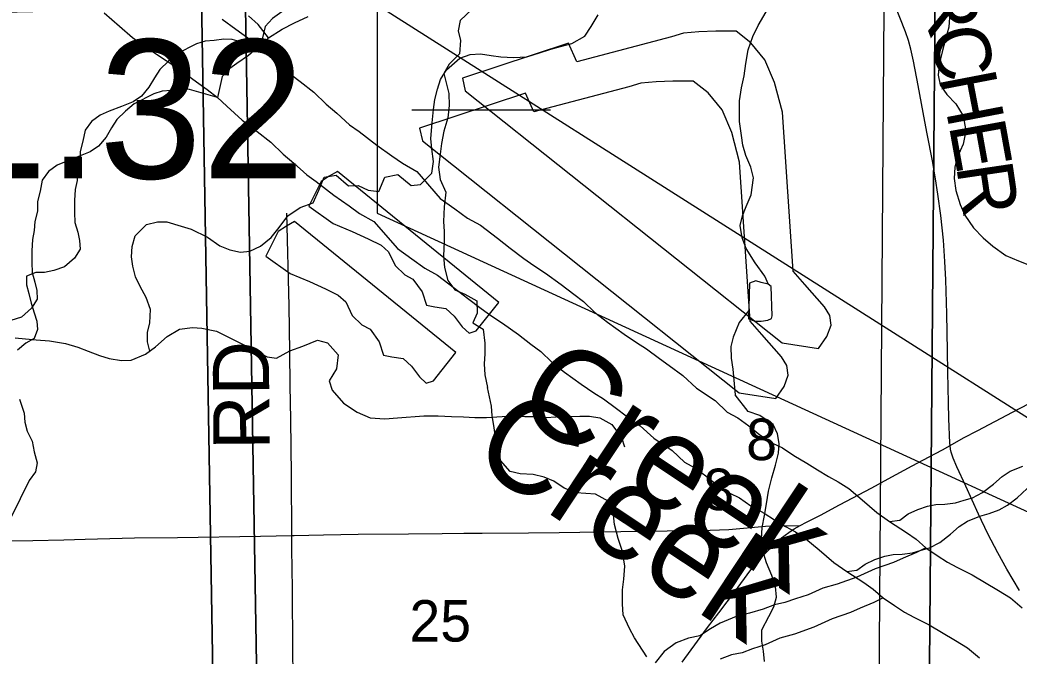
# Model space of a CAD drawing. Extents: x -21.1 to 50.3, y -4.9 to 22.1.
# Drawn here: x 3.578 to 4.587, y 17.259 to 17.902 of the extents above; entities that cross this region are included whole.
import ezdxf

# ---------------------------------------------------------------- set-up
doc = ezdxf.new("R2010")
doc.units = 0
for name, color, linetype in [('GM_X_County_Road', 7, 'Continuous'), ('GM_X_County_Road_Text', 7, 'Continuous'), ('GM_X_Major_River', 7, 'Continuous'), ('GM_X_Major_River_Text', 7, 'Continuous'), ('GM_X_Minor_Lake', 7, 'Continuous'), ('GM_X_Minor_River', 7, 'Continuous'), ('GM_X_Section', 7, 'Continuous'), ('GM_X_Section_Text', 7, 'Continuous'), ('GM_X_Township_Road', 7, 'Continuous'), ('GM_X_Township_Road_Text', 7, 'Continuous'), ('SH_Data', 7, 'Continuous')]:
    doc.layers.add(name, color=color, linetype=linetype)

msp = doc.modelspace()

# ---------------------------------------------------------------- linework, layer by layer
at = {"layer": 'GM_X_County_Road'}
for points in [[(3.853, 17.3809), (3.8526, 17.4422), (3.8524, 17.4702), (3.8521, 17.4981), (3.8515, 17.5323), (3.851, 17.5664), (3.8503, 17.613), (3.848, 17.7066)], [(3.8616, 16.8749), (3.8613, 16.8772), (3.8595, 16.8957), (3.8585, 16.9112), (3.8578, 16.9391), (3.8577, 16.9546), (3.8575, 16.9794), (3.8568, 17.026), (3.8566, 17.0509), (3.8566, 17.0695), (3.8562, 17.1068), (3.856, 17.1316), (3.8555, 17.1627), (3.8551, 17.1875), (3.8548, 17.2154), (3.8541, 17.2651), (3.8536, 17.3273), (3.8531, 17.3677), (3.853, 17.3809)]]:
    msp.add_lwpolyline(points, dxfattribs=at)
at = {"layer": 'GM_X_Major_River'}
for points in [[(3.6634, 17.9087), (3.6791, 17.8952), (3.692, 17.8839), (3.7054, 17.8745), (3.7165, 17.867), (3.726, 17.8606), (3.7394, 17.852), (3.7531, 17.8419), (3.7676, 17.8314), (3.7779, 17.8231), (3.7875, 17.8145), (3.8028, 17.8005), (3.818, 17.7889), (3.8318, 17.778), (3.8444, 17.766), (3.8551, 17.7569), (3.8681, 17.7453), (3.8776, 17.7385), (3.8956, 17.7246), (3.9108, 17.7138), (3.9215, 17.7063), (3.936, 17.698), (3.9598, 17.6709), (3.9743, 17.6604), (3.9872, 17.651), (4.0002, 17.6439), (4.0174, 17.6307), (4.0304, 17.6206), (4.0441, 17.6101), (4.054, 17.603), (4.0658, 17.5955), (4.0819, 17.5838), (4.0945, 17.5741), (4.1044, 17.5669), (4.1155, 17.556), (4.1285, 17.5459), (4.1453, 17.5339), (4.1579, 17.5252), (4.1678, 17.5189), (4.1811, 17.5091), (4.1907, 17.502), (4.2048, 17.4918), (4.2186, 17.4794), (4.2373, 17.4667), (4.2495, 17.455), (4.2602, 17.4494), (4.2712, 17.4411), (4.2823, 17.4321), (4.2953, 17.4239), (4.3052, 17.419), (4.3166, 17.4111), (4.33, 17.4037), (4.3406, 17.3969), (4.3517, 17.3902), (4.3616, 17.3846), (4.3723, 17.3778), (4.3857, 17.3665), (4.4006, 17.3538), (4.4135, 17.3448), (4.4307, 17.3335), (4.4402, 17.3268), (4.4502, 17.3181), (4.4616, 17.3102), (4.4719, 17.3035), (4.4814, 17.2986), (4.4967, 17.2908), (4.5234, 17.2751), (4.5356, 17.2676), (4.5474, 17.2574)], [(3.7826, 17.9025), (3.7964, 17.8924), (3.8109, 17.8819), (3.8212, 17.8736), (3.8308, 17.865), (3.846, 17.8511), (3.8613, 17.8394), (3.8751, 17.8285), (3.8877, 17.8165), (3.8984, 17.8075), (3.9114, 17.7958), (3.9209, 17.789), (3.9389, 17.7752), (3.9541, 17.7643), (3.9648, 17.7568), (3.9793, 17.7485), (4.003, 17.7214), (4.0175, 17.7109), (4.0305, 17.7015), (4.0435, 17.6944), (4.0607, 17.6813), (4.0736, 17.6711), (4.0874, 17.6606), (4.0973, 17.6535), (4.1091, 17.646), (4.1252, 17.6343), (4.1378, 17.6246), (4.1477, 17.6174), (4.1588, 17.6065), (4.1718, 17.5964), (4.1886, 17.5844), (4.2011, 17.5758), (4.2111, 17.5694), (4.2244, 17.5596), (4.234, 17.5525), (4.2481, 17.5424), (4.2618, 17.5299), (4.2805, 17.5172), (4.2928, 17.5055), (4.3034, 17.4999), (4.3145, 17.4917), (4.3256, 17.4826), (4.3386, 17.4744), (4.3485, 17.4695), (4.3599, 17.4617), (4.3732, 17.4542), (4.3839, 17.4474), (4.395, 17.4407), (4.4049, 17.4351), (4.4156, 17.4283), (4.4289, 17.4171), (4.4438, 17.4043), (4.4568, 17.3953), (4.474, 17.384), (4.4835, 17.3773), (4.4935, 17.3686), (4.5049, 17.3607), (4.5152, 17.354), (4.5247, 17.3491), (4.54, 17.3413), (4.5667, 17.3256), (4.5789, 17.3181), (4.5907, 17.3079)]]:
    msp.add_lwpolyline(points, dxfattribs=at)
at = {"layer": 'GM_X_Minor_Lake'}
for points in [[(4.0254, 17.8429), (4.0282, 17.83), (4.3481, 17.5754), (4.385, 17.5698), (4.3935, 17.582), (4.3976, 17.5934), (4.3963, 17.6033), (4.3909, 17.6119), (4.371, 17.6345), (4.3594, 17.648), (4.3485, 17.8084), (4.3406, 17.8383), (4.3309, 17.8613), (4.3166, 17.8786), (4.3017, 17.8903), (4.2812, 17.8904), (4.2642, 17.8895), (4.2486, 17.8882), (4.2366, 17.8846), (4.1409, 17.8593), (4.1323, 17.8782)], [(4.1323, 17.8782), (4.0254, 17.8429)], [(3.9821, 17.7924), (3.9849, 17.7795), (4.3048, 17.5249), (4.3417, 17.5192), (4.3503, 17.5315), (4.3543, 17.5429), (4.353, 17.5527), (4.3476, 17.5614), (4.3277, 17.584), (4.3161, 17.5975), (4.3052, 17.7579), (4.2973, 17.7878), (4.2876, 17.8108), (4.2734, 17.8281), (4.2584, 17.8397), (4.238, 17.8399), (4.2209, 17.839), (4.2054, 17.8376), (4.1933, 17.8341), (4.0976, 17.8088), (4.089, 17.8277)], [(4.089, 17.8277), (3.9821, 17.7924)], [(3.899, 17.7486), (3.8907, 17.7439), (3.8825, 17.7385), (3.8702, 17.7137), (3.8947, 17.6962), (3.9141, 17.688), (3.9301, 17.6806), (3.9431, 17.6743), (3.9508, 17.6675), (3.9574, 17.6536), (3.967, 17.6442), (3.9753, 17.6397), (3.9846, 17.6269), (3.9889, 17.6137), (3.9973, 17.6119), (4.0087, 17.6101), (4.0171, 17.6026), (4.0252, 17.5917), (4.0321, 17.5853), (4.0393, 17.5877), (4.0621, 17.6164)], [(4.0621, 17.6164), (3.899, 17.7486)], [(3.8558, 17.6981), (3.8475, 17.6934), (3.8392, 17.688), (3.8269, 17.6632), (3.8514, 17.6456), (3.8708, 17.6375), (3.8869, 17.6301), (3.8998, 17.6238), (3.9075, 17.617), (3.9141, 17.6031), (3.9237, 17.5937), (3.9321, 17.5892), (3.9413, 17.5764), (3.9456, 17.5632), (3.954, 17.5614), (3.9654, 17.5596), (3.9738, 17.5521), (3.9819, 17.5412), (3.9888, 17.5348), (3.996, 17.5372), (4.0188, 17.5659)], [(4.0188, 17.5659), (3.8558, 17.6981)], [(4.3142, 17.5998), (4.3211, 17.5975), (4.3271, 17.5975), (4.3339, 17.5983), (4.3374, 17.6002), (4.3381, 17.6029), (4.337, 17.6324), (4.334, 17.6347), (4.3271, 17.6366), (4.3215, 17.6381), (4.3154, 17.6359)], [(4.3154, 17.6359), (4.3142, 17.5998)]]:
    msp.add_lwpolyline(points, dxfattribs=at)
at = {"layer": 'GM_X_Minor_River'}
for points in [[(3.8728, 17.9339), (3.8607, 17.9231), (3.8524, 17.9162), (3.8407, 17.9081), (3.8336, 17.9031), (3.8261, 17.895), (3.8212, 17.8736)], [(4.035, 17.9123), (4.0229, 17.9009), (4.021, 17.8907), (4.0233, 17.8808), (4.0225, 17.8672), (4.0119, 17.8569), (4.0066, 17.8474), (4.0088, 17.838), (4.0115, 17.8273), (4.0119, 17.8152), (4.0107, 17.8027), (4.0065, 17.7894), (4.0043, 17.7769), (4.0027, 17.7659), (4.0012, 17.753), (4.0027, 17.7405), (4.0084, 17.7276), (4.0069, 17.7128), (4.0061, 17.698), (4.0069, 17.6878), (4.0069, 17.6775), (4.0061, 17.6635), (4.0072, 17.6517), (4.0106, 17.6385), (4.0178, 17.629), (4.0277, 17.6248), (4.0398, 17.618), (4.0402, 17.6055), (4.036, 17.5956), (4.0462, 17.5892), (4.0481, 17.5751), (4.0481, 17.5645), (4.0474, 17.5543), (4.0481, 17.5433), (4.0508, 17.5304)], [(3.7096, 17.5673), (3.7072, 17.5766), (3.7073, 17.5861), (3.7097, 17.5959), (3.7103, 17.6092), (3.706, 17.6214), (3.6997, 17.6325), (3.6953, 17.6421), (3.6924, 17.6528), (3.691, 17.6623), (3.6916, 17.6729), (3.6948, 17.6835), (3.7063, 17.6951), (3.7174, 17.6976), (3.7269, 17.6978), (3.7413, 17.6934), (3.7515, 17.6902), (3.7677, 17.6824), (3.7804, 17.6735), (3.7903, 17.6695), (3.8012, 17.6671), (3.8107, 17.6681), (3.8215, 17.6732), (3.8322, 17.6818), (3.8404, 17.6919), (3.8489, 17.7039), (3.8616, 17.7121), (3.8746, 17.7169), (3.8804, 17.7297), (3.8856, 17.7429), (3.8978, 17.745), (3.9101, 17.7342), (3.92, 17.7344), (3.9302, 17.7297), (3.9408, 17.7284), (3.9471, 17.7427), (3.9601, 17.7456), (3.9736, 17.7343), (3.9831, 17.7353), (3.9943, 17.747), (3.996, 17.7587), (3.9943, 17.7716), (3.9933, 17.7819), (3.9947, 17.7978), (3.996, 17.8111), (3.9973, 17.8214), (4.0001, 17.8316), (4.0033, 17.8414), (4.0092, 17.8512), (4.0227, 17.8631), (4.033, 17.8668), (4.0436, 17.8674), (4.0542, 17.8657), (4.0641, 17.8644), (4.077, 17.8638), (4.0903, 17.8644), (4.1033, 17.8684), (4.1147, 17.872), (4.1243, 17.8749), (4.1357, 17.8778), (4.1491, 17.8852), (4.1553, 17.8949), (4.1624, 17.9066)], [(3.8295, 17.8834), (3.8189, 17.897), (3.8093, 17.9057)], [(3.8295, 17.8834), (3.8433, 17.8922), (3.8558, 17.8988), (3.8694, 17.905)], [(4.3343, 17.6345), (4.3306, 17.6427), (4.3211, 17.6563), (4.312, 17.6707), (4.3078, 17.6814), (4.3059, 17.6939), (4.3082, 17.7037), (4.312, 17.7132), (4.317, 17.725), (4.3192, 17.742), (4.3166, 17.753), (4.3117, 17.7648), (4.3086, 17.775), (4.3071, 17.7849), (4.3052, 17.7989), (4.3052, 17.8092), (4.3053, 17.8198), (4.3072, 17.8331), (4.3098, 17.8452), (4.3117, 17.8577), (4.314, 17.8714), (4.3186, 17.8847), (4.3239, 17.896), (4.3322, 17.9097)], [(4.5174, 17.9039), (4.5165, 17.8944), (4.5133, 17.8823)], [(3.8212, 17.8736), (3.7929, 17.8818), (3.7845, 17.8821), (3.7746, 17.8809), (3.7655, 17.8801), (3.7567, 17.8774), (3.737, 17.8674), (3.7283, 17.8598), (3.7196, 17.8514), (3.7143, 17.843), (3.7086, 17.8338), (3.7011, 17.8247), (3.6927, 17.8189), (3.681, 17.8143), (3.6684, 17.8093), (3.6593, 17.8055), (3.6506, 17.7989), (3.6442, 17.7902), (3.642, 17.7791), (3.6394, 17.7689), (3.6394, 17.759), (3.6368, 17.7487), (3.6361, 17.7396), (3.6342, 17.7305), (3.6335, 17.7191), (3.6336, 17.7073), (3.634, 17.697), (3.6368, 17.6872), (3.6387, 17.6788), (3.6391, 17.6701), (3.6335, 17.661), (3.6233, 17.6522), (3.6126, 17.6487), (3.6031, 17.6467), (3.5944, 17.6467), (3.5849, 17.6428), (3.5849, 17.6341), (3.5873, 17.6254), (3.5896, 17.6155), (3.5927, 17.606), (3.5954, 17.5973), (3.5962, 17.5889), (3.5928, 17.5798), (3.5845, 17.5752), (3.5758, 17.5683)], [(3.8295, 17.8834), (3.8174, 17.8726), (3.8091, 17.8656), (3.7975, 17.8576), (3.7903, 17.8525), (3.7828, 17.8445), (3.7779, 17.8231)], [(4.5133, 17.8823), (4.5097, 17.8694), (4.5068, 17.8566), (4.5059, 17.8459), (4.5077, 17.836), (4.5147, 17.8264), (4.5237, 17.8168), (4.5311, 17.8049), (4.5339, 17.7897), (4.531, 17.776), (4.5251, 17.7628), (4.5227, 17.753), (4.5221, 17.7416), (4.5235, 17.7294), (4.5282, 17.7153), (4.5326, 17.7046), (4.5415, 17.6915), (4.5512, 17.6815), (4.561, 17.673), (4.5741, 17.6637), (4.5869, 17.6582), (4.6013, 17.6527)], [(3.7779, 17.8231), (3.7496, 17.8313), (3.7412, 17.8316), (3.7313, 17.8304), (3.7222, 17.8296), (3.7135, 17.8269), (3.6937, 17.8169), (3.685, 17.8093), (3.6763, 17.8009), (3.671, 17.7925), (3.6654, 17.7833), (3.6578, 17.7742), (3.6495, 17.7684), (3.6377, 17.7638), (3.6251, 17.7588), (3.616, 17.7549), (3.6073, 17.7484), (3.6009, 17.7397), (3.5987, 17.7286), (3.5961, 17.7184), (3.5961, 17.7085), (3.5935, 17.6982), (3.5928, 17.6891), (3.591, 17.68), (3.5903, 17.6686), (3.5903, 17.6568), (3.5908, 17.6465), (3.5935, 17.6367), (3.5954, 17.6283), (3.5959, 17.6196), (3.5902, 17.6104), (3.58, 17.6016), (3.5693, 17.5982)], [(4.3145, 17.6082), (4.3048, 17.596), (4.2987, 17.5812), (4.2964, 17.5718), (4.2968, 17.56), (4.2983, 17.549), (4.2994, 17.538), (4.3009, 17.5232)], [(3.5735, 17.5805), (3.5841, 17.5796), (3.5948, 17.5786), (3.6084, 17.5777), (3.6243, 17.5748), (3.6368, 17.5712), (3.6474, 17.5672), (3.6587, 17.5629), (3.6685, 17.5597), (3.681, 17.5576), (3.6909, 17.5582), (3.7051, 17.5641), (3.7154, 17.5715), (3.727, 17.582), (3.7396, 17.5894), (3.7526, 17.5911), (3.7621, 17.5905), (3.7768, 17.5873), (3.8025, 17.5747), (3.813, 17.5696), (3.8281, 17.5614), (3.8376, 17.5601), (3.851, 17.5675), (3.864, 17.5723), (3.8789, 17.5781), (3.8891, 17.5757), (3.8999, 17.5634), (3.8982, 17.5493), (3.8908, 17.5373), (3.8936, 17.5278), (3.9052, 17.5147), (3.9191, 17.5057), (3.9323, 17.4998), (3.9471, 17.4988), (3.9597, 17.4998), (3.9863, 17.5017), (4.0007, 17.5018), (4.0144, 17.5012), (4.0265, 17.5007), (4.0379, 17.5001), (4.0497, 17.5003), (4.0653, 17.5012), (4.0748, 17.5018), (4.0885, 17.5013), (4.0987, 17.5011), (4.1097, 17.5002), (4.12, 17.5008), (4.1325, 17.5013), (4.1439, 17.5016), (4.1538, 17.5014), (4.164, 17.4997), (4.1761, 17.4931), (4.1861, 17.48), (4.189, 17.4705)], [(4.2117, 17.2586), (4.199, 17.2776), (4.1941, 17.2872), (4.1877, 17.3009), (4.187, 17.3119), (4.1871, 17.3263), (4.1883, 17.3369), (4.1892, 17.3502), (4.187, 17.365), (4.1825, 17.3779), (4.1788, 17.392), (4.1778, 17.4018), (4.1733, 17.4155), (4.1597, 17.4228), (4.1498, 17.4233), (4.1403, 17.4241), (4.1282, 17.4287), (4.1176, 17.436), (4.1078, 17.4398), (4.0968, 17.4426), (4.0835, 17.4434), (4.0737, 17.4457), (4.0639, 17.4568), (4.0602, 17.4701), (4.0584, 17.4826), (4.0569, 17.4921), (4.0555, 17.502), (4.0548, 17.5115), (4.0508, 17.5304)], [(3.578, 17.5186), (3.5826, 17.5045), (3.5834, 17.4954), (3.5858, 17.4863), (3.5908, 17.4761), (3.5927, 17.4655), (3.5958, 17.4545), (3.594, 17.4453), (3.5879, 17.4366), (3.5694, 17.3996)], [(4.3305, 17.2537), (4.3294, 17.2643), (4.3276, 17.2742), (4.3276, 17.2856), (4.3349, 17.2992), (4.3399, 17.309), (4.3427, 17.3189), (4.3416, 17.3295), (4.3379, 17.3405), (4.3323, 17.3535), (4.3289, 17.3656), (4.3275, 17.3778), (4.3279, 17.3892), (4.3303, 17.4013), (4.3323, 17.413), (4.3346, 17.4259), (4.3378, 17.4392), (4.3416, 17.4521), (4.3444, 17.4642), (4.3452, 17.474), (4.3437, 17.4835), (4.3393, 17.493), (4.3257, 17.5022), (4.3139, 17.5061), (4.3009, 17.5232)], [(4.4568, 17.3953), (4.4671, 17.3966), (4.4754, 17.4028), (4.4853, 17.4074), (4.4952, 17.4105), (4.5035, 17.4124), (4.5127, 17.4128), (4.5233, 17.414), (4.532, 17.4168), (4.5404, 17.4191), (4.5507, 17.4245), (4.5616, 17.4329), (4.5704, 17.4405), (4.5787, 17.4459), (4.5912, 17.4509)], [(4.4135, 17.3448), (4.4238, 17.3461), (4.4321, 17.3522), (4.442, 17.3569), (4.4519, 17.36), (4.4602, 17.3619), (4.4694, 17.3623), (4.48, 17.3635), (4.4888, 17.3662), (4.4971, 17.3686), (4.5074, 17.3739), (4.5184, 17.3824), (4.5271, 17.39), (4.5354, 17.3954), (4.5479, 17.4004), (4.5574, 17.4031), (4.5673, 17.4069), (4.5757, 17.4115), (4.5855, 17.4192), (4.5957, 17.4284)], [(4.4935, 17.3686), (4.484, 17.364), (4.4704, 17.3582), (4.4606, 17.3539), (4.4421, 17.3472), (4.4236, 17.3391), (4.4039, 17.332), (4.3892, 17.3277), (4.3745, 17.3211), (4.3616, 17.3172), (4.351, 17.3133), (4.3405, 17.3109), (4.3291, 17.3066), (4.3151, 17.3026), (4.3019, 17.2991), (4.2857, 17.2924), (4.2759, 17.2866), (4.265, 17.2797), (4.2536, 17.2773), (4.2411, 17.2726), (4.2291, 17.2638), (4.2201, 17.2523)], [(4.4502, 17.3181), (4.4407, 17.3135), (4.4271, 17.3077), (4.4173, 17.3034), (4.3988, 17.2967), (4.3803, 17.2886), (4.3606, 17.2815), (4.3459, 17.2772), (4.3312, 17.2706), (4.3183, 17.2667), (4.3078, 17.2627), (4.2972, 17.2604), (4.2858, 17.2561)]]:
    msp.add_lwpolyline(points, dxfattribs=at)
at = {"layer": 'GM_X_Section'}
for points in [[(4.4529, 18.1426), (5.4574, 18.1459), (5.4527, 17.1308), (4.4456, 17.1337)], [(2.7666, 18.0085), (3.8045, 18.0148), (3.8217, 16.9904), (2.7797, 16.9773), (2.7786, 17.0292), (2.7674, 17.957)], [(3.8045, 18.0148), (4.8343, 17.9854), (4.8468, 16.9686), (4.4335, 16.9849), (3.8217, 16.9904)], [(4.5025, 17.9889), (5.4882, 17.9725), (5.5202, 16.9439), (4.4943, 16.9302), (4.5029, 17.9298)], [(2.7233, 17.958), (3.7612, 17.9643), (3.7784, 16.9399), (2.7365, 16.9268), (2.7353, 16.9787), (2.7241, 17.9065)], [(3.7612, 17.9643), (4.791, 17.9349), (4.8035, 16.9181), (4.3903, 16.9344), (3.7784, 16.9399)], [(3.4809, 17.9078), (4.5029, 17.9298), (4.4943, 16.9302), (4.4944, 16.9022), (3.4856, 16.8942)]]:
    msp.add_lwpolyline(points, close=True, dxfattribs=at)
at = {"layer": 'GM_X_Township_Road'}
for points in [[(4.5179, 17.4718), (4.5177, 17.4744), (4.5166, 17.4993), (4.5161, 17.5148), (4.5155, 17.5459), (4.5153, 17.5676), (4.5146, 17.6049), (4.5136, 17.6391), (4.5126, 17.6577), (4.5112, 17.6792), (4.5085, 17.7041), (4.5054, 17.7256), (4.5032, 17.741), (4.5001, 17.7593), (4.4948, 17.7867), (4.4923, 17.7989), (4.4855, 17.8355), (4.481, 17.86), (4.4783, 17.872), (4.4758, 17.8809), (4.4728, 17.8896), (4.4614, 17.9185)], [(4.5179, 17.4718), (4.5314, 17.4795), (4.5459, 17.4871), (4.581, 17.5057), (4.606, 17.5187), (4.6251, 17.5292), (4.6444, 17.5398), (4.674, 17.5554), (4.693, 17.5658), (4.7229, 17.582), (4.7444, 17.5946), (4.7627, 17.6063), (4.7788, 17.6175), (4.8058, 17.6365), (4.8212, 17.6472), (4.8314, 17.6544), (4.8513, 17.6687), (4.8646, 17.6776), (4.8804, 17.6875)], [(4.3666, 17.3912), (4.3729, 17.3944), (4.3869, 17.4017), (4.406, 17.4119), (4.4389, 17.4293), (4.4552, 17.4382), (4.4794, 17.4513), (4.4966, 17.4605), (4.5101, 17.4675), (4.5179, 17.4718)], [(4.5878, 17.3256), (4.5751, 17.347), (4.5661, 17.3634), (4.5561, 17.3828), (4.5467, 17.4024), (4.5338, 17.4307), (4.5246, 17.4504), (4.5209, 17.459), (4.5189, 17.465), (4.5183, 17.4681), (4.5179, 17.4718)], [(3.853, 17.3809), (3.8554, 17.381), (3.8849, 17.3816), (3.9201, 17.3823), (3.9707, 17.3826), (4.0049, 17.3831), (4.0267, 17.3833), (4.0454, 17.3835), (4.092, 17.3838), (4.1231, 17.3839), (4.1854, 17.385), (4.232, 17.3856), (4.2756, 17.3864), (4.2943, 17.3872), (4.3129, 17.3888), (4.3315, 17.3903), (4.3434, 17.3907), (4.3666, 17.3912)], [(4.2473, 17.2531), (4.2565, 17.2656), (4.2729, 17.288), (4.2843, 17.303), (4.3011, 17.3252), (4.3155, 17.3451), (4.3235, 17.3546), (4.3273, 17.3591), (4.3337, 17.3656), (4.3405, 17.3724), (4.3477, 17.3785), (4.355, 17.3842), (4.3605, 17.3878), (4.3666, 17.3912)], [(3.5544, 17.3755), (3.5916, 17.3759), (3.6227, 17.3768), (3.6444, 17.3774), (3.6941, 17.3785), (3.7376, 17.3791), (3.8214, 17.3804), (3.853, 17.3809)]]:
    msp.add_lwpolyline(points, dxfattribs=at)
at = {"layer": 'SH_Data'}
msp.add_line((3.9742, 17.8107), (4.1142, 17.8107), dxfattribs=at)
msp.add_lwpolyline([(3.9392, 17.7066), (5.136, 17.1573), (3.9392, 17.9166)], close=True, dxfattribs=at)

# ---------------------------------------------------------------- texts
at = {"layer": 'GM_X_County_Road_Text'}
msp.add_text('RD', height=0.05682, rotation=90.4934, dxfattribs=at).set_placement((3.8307, 17.4678))
at = {"layer": 'GM_X_Major_River_Text'}
for p in [(4.0741, 17.5077), (4.0308, 17.4572)]:
    msp.add_text('Creek', height=0.09472, rotation=326.4647, dxfattribs=at).set_placement(p)
at = {"layer": 'GM_X_Section_Text'}
for s, height, p in [('8', 0.0419, (4.3119, 17.4571)), ('8', 0.0419, (4.2686, 17.4066)), ('25', 0.04186, (3.9718, 17.2739))]:
    msp.add_text(s, height=height, rotation=0, dxfattribs=at).set_placement(p)
at = {"layer": 'GM_X_Township_Road_Text'}
for s, rotation, p in [('R', 290.7084, (4.4803, 17.931)), ('C', 283.4356, (4.4963, 17.8892)), ('H', 280.8992, (4.507, 17.8444)), ('E', 280.2194, (4.5164, 17.7955)), ('R', 278.4138, (4.5239, 17.7542))]:
    msp.add_text(s, height=0.0568, rotation=rotation, dxfattribs=at).set_placement(p)
at = {"layer": 'SH_Data'}
msp.add_text('WAY-241-1.32', height=0.14, dxfattribs=at).set_placement((2.6386, 17.7416))

doc.saveas('drawing.dxf')
